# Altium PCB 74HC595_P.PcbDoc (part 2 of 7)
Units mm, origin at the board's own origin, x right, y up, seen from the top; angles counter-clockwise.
Board outline 89.11 x 89.03 mm, 2 copper layers (Top Layer, Bottom Layer); 552 components, 23 nets, 1488 pads, 408 vias.
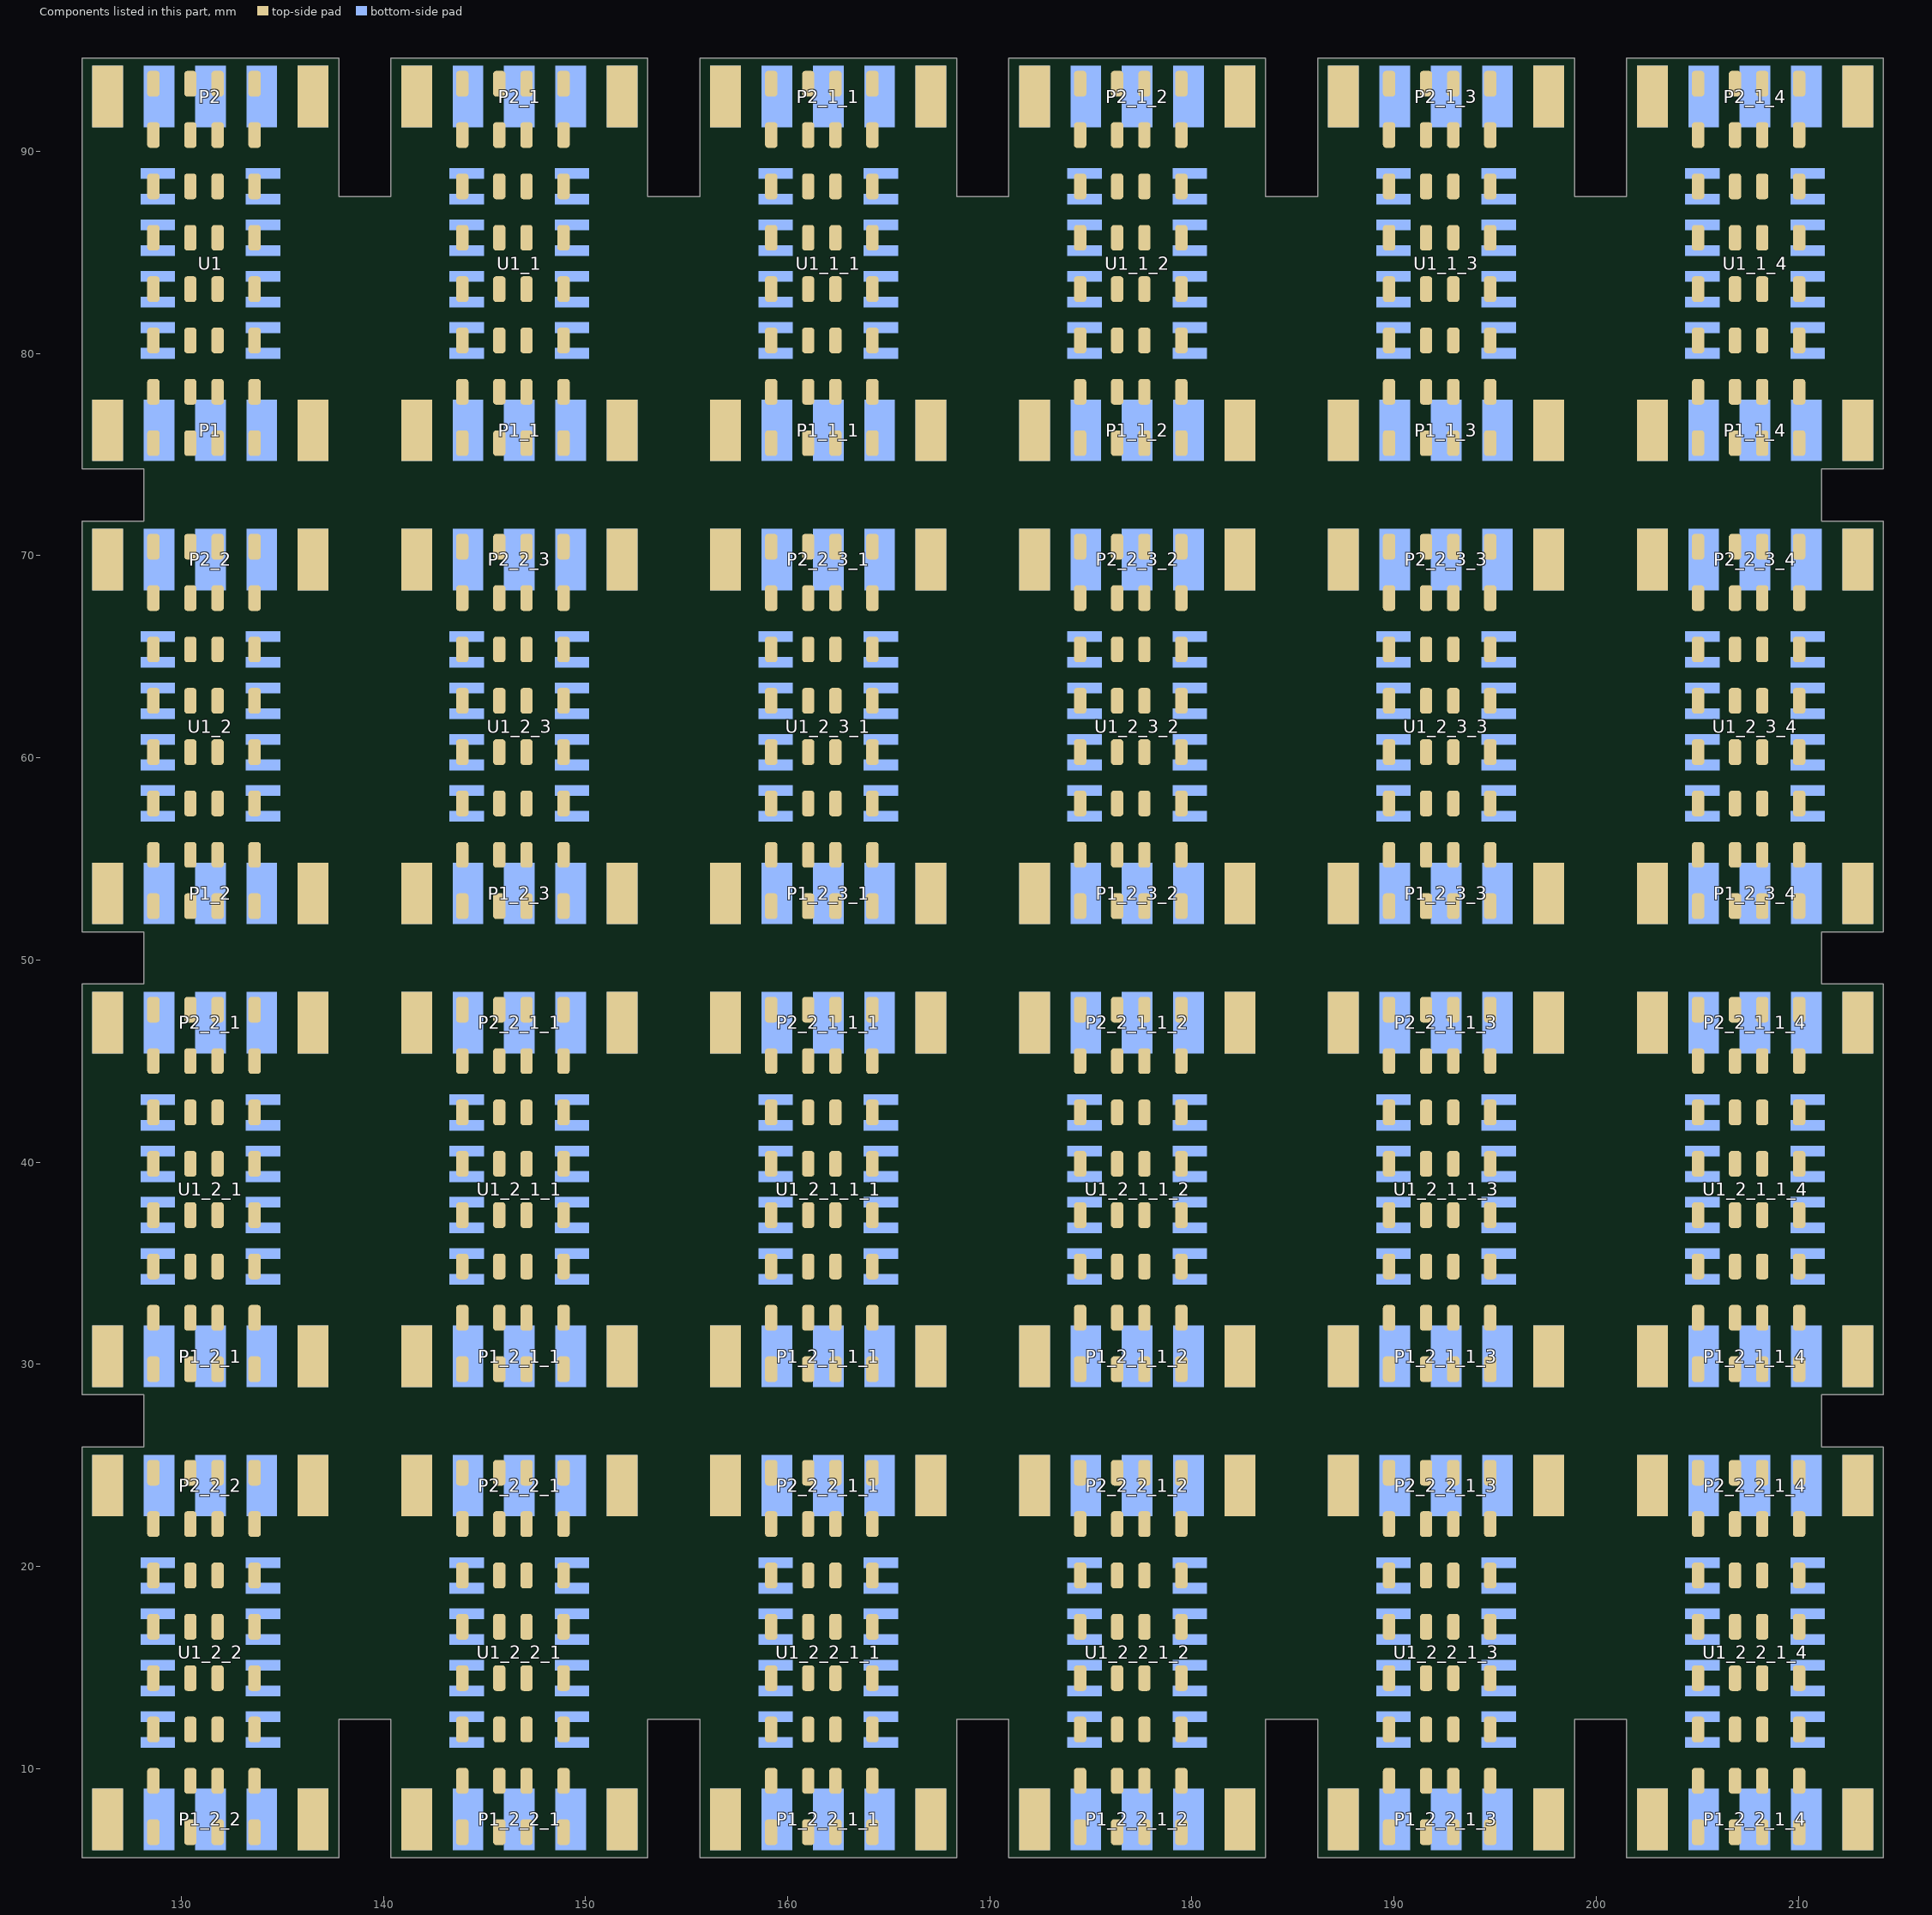
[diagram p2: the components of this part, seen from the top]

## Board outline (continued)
cut-out: 185.821,14.606 ccw(c186.096,14.606) 186.096,14.331 ccw(c186.096,14.606) 186.371,14.606 ccw(c186.096,14.606) 186.096,14.881 ccw(c186.096,14.606)
cut-out: 185.821,15.368 ccw(c186.096,15.368) 186.096,15.093 ccw(c186.096,15.368) 186.371,15.368 ccw(c186.096,15.368) 186.096,15.643 ccw(c186.096,15.368)
cut-out: 168.211,18.416 ccw(c168.486,18.416) 168.486,18.141 ccw(c168.486,18.416) 168.761,18.416 ccw(c168.486,18.416) 168.486,18.691 ccw(c168.486,18.416)
cut-out: 170.539,18.416 ccw(c170.814,18.416) 170.814,18.141 ccw(c170.814,18.416) 171.089,18.416 ccw(c170.814,18.416) 170.814,18.691 ccw(c170.814,18.416)
cut-out: 168.211,17.654 ccw(c168.486,17.654) 168.486,17.379 ccw(c168.486,17.654) 168.761,17.654 ccw(c168.486,17.654) 168.486,17.929 ccw(c168.486,17.654)
cut-out: 170.539,16.892 cw(c170.814,16.892) 170.814,17.167 cw(c170.814,16.892) 171.089,16.892 cw(c170.814,16.892) 170.814,16.617 cw(c170.814,16.892)
cut-out: 170.539,17.654 ccw(c170.814,17.654) 170.814,17.379 ccw(c170.814,17.654) 171.089,17.654 ccw(c170.814,17.654) 170.814,17.929 ccw(c170.814,17.654)
cut-out: 170.539,16.13 ccw(c170.814,16.13) 170.814,15.855 ccw(c170.814,16.13) 171.089,16.13 ccw(c170.814,16.13) 170.814,16.405 ccw(c170.814,16.13)
cut-out: 168.211,16.13 ccw(c168.486,16.13) 168.486,15.855 ccw(c168.486,16.13) 168.761,16.13 ccw(c168.486,16.13) 168.486,16.405 ccw(c168.486,16.13)
cut-out: 168.211,16.892 ccw(c168.486,16.892) 168.486,16.617 ccw(c168.486,16.892) 168.761,16.892 ccw(c168.486,16.892) 168.486,17.167 ccw(c168.486,16.892)
cut-out: 168.211,15.368 ccw(c168.486,15.368) 168.486,15.093 ccw(c168.486,15.368) 168.761,15.368 ccw(c168.486,15.368) 168.486,15.643 ccw(c168.486,15.368)
cut-out: 168.211,14.606 ccw(c168.486,14.606) 168.486,14.331 ccw(c168.486,14.606) 168.761,14.606 ccw(c168.486,14.606) 168.486,14.881 ccw(c168.486,14.606)
cut-out: 168.211,13.844 ccw(c168.486,13.844) 168.486,13.569 ccw(c168.486,13.844) 168.761,13.844 ccw(c168.486,13.844) 168.486,14.119 ccw(c168.486,13.844)
cut-out: 168.211,13.082 ccw(c168.486,13.082) 168.486,12.807 ccw(c168.486,13.082) 168.761,13.082 ccw(c168.486,13.082) 168.486,13.357 ccw(c168.486,13.082)
cut-out: 170.539,13.082 ccw(c170.814,13.082) 170.814,12.807 ccw(c170.814,13.082) 171.089,13.082 ccw(c170.814,13.082) 170.814,13.357 ccw(c170.814,13.082)
cut-out: 170.539,13.844 ccw(c170.814,13.844) 170.814,13.569 ccw(c170.814,13.844) 171.089,13.844 ccw(c170.814,13.844) 170.814,14.119 ccw(c170.814,13.844)
cut-out: 170.539,14.606 ccw(c170.814,14.606) 170.814,14.331 ccw(c170.814,14.606) 171.089,14.606 ccw(c170.814,14.606) 170.814,14.881 ccw(c170.814,14.606)
cut-out: 170.539,15.368 ccw(c170.814,15.368) 170.814,15.093 ccw(c170.814,15.368) 171.089,15.368 ccw(c170.814,15.368) 170.814,15.643 ccw(c170.814,15.368)
cut-out: 152.929,18.416 ccw(c153.204,18.416) 153.204,18.141 ccw(c153.204,18.416) 153.479,18.416 ccw(c153.204,18.416) 153.204,18.691 ccw(c153.204,18.416)
cut-out: 155.257,18.416 ccw(c155.532,18.416) 155.532,18.141 ccw(c155.532,18.416) 155.807,18.416 ccw(c155.532,18.416) 155.532,18.691 ccw(c155.532,18.416)
cut-out: 152.929,17.654 ccw(c153.204,17.654) 153.204,17.379 ccw(c153.204,17.654) 153.479,17.654 ccw(c153.204,17.654) 153.204,17.929 ccw(c153.204,17.654)
cut-out: 155.257,16.892 cw(c155.532,16.892) 155.532,17.167 cw(c155.532,16.892) 155.807,16.892 cw(c155.532,16.892) 155.532,16.617 cw(c155.532,16.892)
cut-out: 155.257,17.654 ccw(c155.532,17.654) 155.532,17.379 ccw(c155.532,17.654) 155.807,17.654 ccw(c155.532,17.654) 155.532,17.929 ccw(c155.532,17.654)
cut-out: 155.257,16.13 ccw(c155.532,16.13) 155.532,15.855 ccw(c155.532,16.13) 155.807,16.13 ccw(c155.532,16.13) 155.532,16.405 ccw(c155.532,16.13)
cut-out: 152.929,16.13 ccw(c153.204,16.13) 153.204,15.855 ccw(c153.204,16.13) 153.479,16.13 ccw(c153.204,16.13) 153.204,16.405 ccw(c153.204,16.13)
cut-out: 152.929,16.892 ccw(c153.204,16.892) 153.204,16.617 ccw(c153.204,16.892) 153.479,16.892 ccw(c153.204,16.892) 153.204,17.167 ccw(c153.204,16.892)
cut-out: 152.929,15.368 ccw(c153.204,15.368) 153.204,15.093 ccw(c153.204,15.368) 153.479,15.368 ccw(c153.204,15.368) 153.204,15.643 ccw(c153.204,15.368)
cut-out: 152.929,14.606 ccw(c153.204,14.606) 153.204,14.331 ccw(c153.204,14.606) 153.479,14.606 ccw(c153.204,14.606) 153.204,14.881 ccw(c153.204,14.606)
cut-out: 152.929,13.844 ccw(c153.204,13.844) 153.204,13.569 ccw(c153.204,13.844) 153.479,13.844 ccw(c153.204,13.844) 153.204,14.119 ccw(c153.204,13.844)
cut-out: 152.929,13.082 ccw(c153.204,13.082) 153.204,12.807 ccw(c153.204,13.082) 153.479,13.082 ccw(c153.204,13.082) 153.204,13.357 ccw(c153.204,13.082)
cut-out: 155.257,13.082 ccw(c155.532,13.082) 155.532,12.807 ccw(c155.532,13.082) 155.807,13.082 ccw(c155.532,13.082) 155.532,13.357 ccw(c155.532,13.082)
cut-out: 155.257,13.844 ccw(c155.532,13.844) 155.532,13.569 ccw(c155.532,13.844) 155.807,13.844 ccw(c155.532,13.844) 155.532,14.119 ccw(c155.532,13.844)
cut-out: 155.257,14.606 ccw(c155.532,14.606) 155.532,14.331 ccw(c155.532,14.606) 155.807,14.606 ccw(c155.532,14.606) 155.532,14.881 ccw(c155.532,14.606)
cut-out: 155.257,15.368 ccw(c155.532,15.368) 155.532,15.093 ccw(c155.532,15.368) 155.807,15.368 ccw(c155.532,15.368) 155.532,15.643 ccw(c155.532,15.368)
cut-out: 137.647,18.416 ccw(c137.922,18.416) 137.922,18.141 ccw(c137.922,18.416) 138.197,18.416 ccw(c137.922,18.416) 137.922,18.691 ccw(c137.922,18.416)
cut-out: 139.975,18.416 ccw(c140.25,18.416) 140.25,18.141 ccw(c140.25,18.416) 140.525,18.416 ccw(c140.25,18.416) 140.25,18.691 ccw(c140.25,18.416)
cut-out: 137.647,17.654 ccw(c137.922,17.654) 137.922,17.379 ccw(c137.922,17.654) 138.197,17.654 ccw(c137.922,17.654) 137.922,17.929 ccw(c137.922,17.654)
cut-out: 139.975,16.892 cw(c140.25,16.892) 140.25,17.167 cw(c140.25,16.892) 140.525,16.892 cw(c140.25,16.892) 140.25,16.617 cw(c140.25,16.892)
cut-out: 139.975,17.654 ccw(c140.25,17.654) 140.25,17.379 ccw(c140.25,17.654) 140.525,17.654 ccw(c140.25,17.654) 140.25,17.929 ccw(c140.25,17.654)
cut-out: 139.975,16.13 ccw(c140.25,16.13) 140.25,15.855 ccw(c140.25,16.13) 140.525,16.13 ccw(c140.25,16.13) 140.25,16.405 ccw(c140.25,16.13)
cut-out: 137.647,16.13 ccw(c137.922,16.13) 137.922,15.855 ccw(c137.922,16.13) 138.197,16.13 ccw(c137.922,16.13) 137.922,16.405 ccw(c137.922,16.13)
cut-out: 137.647,16.892 ccw(c137.922,16.892) 137.922,16.617 ccw(c137.922,16.892) 138.197,16.892 ccw(c137.922,16.892) 137.922,17.167 ccw(c137.922,16.892)
cut-out: 137.647,15.368 ccw(c137.922,15.368) 137.922,15.093 ccw(c137.922,15.368) 138.197,15.368 ccw(c137.922,15.368) 137.922,15.643 ccw(c137.922,15.368)
cut-out: 137.647,14.606 ccw(c137.922,14.606) 137.922,14.331 ccw(c137.922,14.606) 138.197,14.606 ccw(c137.922,14.606) 137.922,14.881 ccw(c137.922,14.606)
cut-out: 137.647,13.844 ccw(c137.922,13.844) 137.922,13.569 ccw(c137.922,13.844) 138.197,13.844 ccw(c137.922,13.844) 137.922,14.119 ccw(c137.922,13.844)
cut-out: 137.647,13.082 ccw(c137.922,13.082) 137.922,12.807 ccw(c137.922,13.082) 138.197,13.082 ccw(c137.922,13.082) 137.922,13.357 ccw(c137.922,13.082)
cut-out: 139.975,13.082 ccw(c140.25,13.082) 140.25,12.807 ccw(c140.25,13.082) 140.525,13.082 ccw(c140.25,13.082) 140.25,13.357 ccw(c140.25,13.082)
cut-out: 139.975,13.844 ccw(c140.25,13.844) 140.25,13.569 ccw(c140.25,13.844) 140.525,13.844 ccw(c140.25,13.844) 140.25,14.119 ccw(c140.25,13.844)
cut-out: 139.975,14.606 ccw(c140.25,14.606) 140.25,14.331 ccw(c140.25,14.606) 140.525,14.606 ccw(c140.25,14.606) 140.25,14.881 ccw(c140.25,14.606)
cut-out: 139.975,15.368 ccw(c140.25,15.368) 140.25,15.093 ccw(c140.25,15.368) 140.525,15.368 ccw(c140.25,15.368) 140.25,15.643 ccw(c140.25,15.368)
cut-out: 198.775,41.318 ccw(c199.05,41.318) 199.05,41.043 ccw(c199.05,41.318) 199.325,41.318 ccw(c199.05,41.318) 199.05,41.593 ccw(c199.05,41.318)
cut-out: 201.103,41.318 ccw(c201.378,41.318) 201.378,41.043 ccw(c201.378,41.318) 201.653,41.318 ccw(c201.378,41.318) 201.378,41.593 ccw(c201.378,41.318)
cut-out: 198.775,40.556 ccw(c199.05,40.556) 199.05,40.281 ccw(c199.05,40.556) 199.325,40.556 ccw(c199.05,40.556) 199.05,40.831 ccw(c199.05,40.556)
cut-out: 201.103,39.794 cw(c201.378,39.794) 201.378,40.069 cw(c201.378,39.794) 201.653,39.794 cw(c201.378,39.794) 201.378,39.519 cw(c201.378,39.794)
cut-out: 201.103,40.556 ccw(c201.378,40.556) 201.378,40.281 ccw(c201.378,40.556) 201.653,40.556 ccw(c201.378,40.556) 201.378,40.831 ccw(c201.378,40.556)
cut-out: 201.103,39.032 ccw(c201.378,39.032) 201.378,38.757 ccw(c201.378,39.032) 201.653,39.032 ccw(c201.378,39.032) 201.378,39.307 ccw(c201.378,39.032)
cut-out: 198.775,39.032 ccw(c199.05,39.032) 199.05,38.757 ccw(c199.05,39.032) 199.325,39.032 ccw(c199.05,39.032) 199.05,39.307 ccw(c199.05,39.032)
cut-out: 198.775,39.794 ccw(c199.05,39.794) 199.05,39.519 ccw(c199.05,39.794) 199.325,39.794 ccw(c199.05,39.794) 199.05,40.069 ccw(c199.05,39.794)
cut-out: 198.775,38.27 ccw(c199.05,38.27) 199.05,37.995 ccw(c199.05,38.27) 199.325,38.27 ccw(c199.05,38.27) 199.05,38.545 ccw(c199.05,38.27)
cut-out: 198.775,37.508 ccw(c199.05,37.508) 199.05,37.233 ccw(c199.05,37.508) 199.325,37.508 ccw(c199.05,37.508) 199.05,37.783 ccw(c199.05,37.508)
cut-out: 198.775,36.746 ccw(c199.05,36.746) 199.05,36.471 ccw(c199.05,36.746) 199.325,36.746 ccw(c199.05,36.746) 199.05,37.021 ccw(c199.05,36.746)
cut-out: 198.775,35.984 ccw(c199.05,35.984) 199.05,35.709 ccw(c199.05,35.984) 199.325,35.984 ccw(c199.05,35.984) 199.05,36.259 ccw(c199.05,35.984)
cut-out: 201.103,35.984 ccw(c201.378,35.984) 201.378,35.709 ccw(c201.378,35.984) 201.653,35.984 ccw(c201.378,35.984) 201.378,36.259 ccw(c201.378,35.984)
cut-out: 201.103,36.746 ccw(c201.378,36.746) 201.378,36.471 ccw(c201.378,36.746) 201.653,36.746 ccw(c201.378,36.746) 201.378,37.021 ccw(c201.378,36.746)
cut-out: 201.103,37.508 ccw(c201.378,37.508) 201.378,37.233 ccw(c201.378,37.508) 201.653,37.508 ccw(c201.378,37.508) 201.378,37.783 ccw(c201.378,37.508)
cut-out: 201.103,38.27 ccw(c201.378,38.27) 201.378,37.995 ccw(c201.378,38.27) 201.653,38.27 ccw(c201.378,38.27) 201.378,38.545 ccw(c201.378,38.27)
cut-out: 183.493,41.318 ccw(c183.768,41.318) 183.768,41.043 ccw(c183.768,41.318) 184.043,41.318 ccw(c183.768,41.318) 183.768,41.593 ccw(c183.768,41.318)
cut-out: 185.821,41.318 ccw(c186.096,41.318) 186.096,41.043 ccw(c186.096,41.318) 186.371,41.318 ccw(c186.096,41.318) 186.096,41.593 ccw(c186.096,41.318)
cut-out: 183.493,40.556 ccw(c183.768,40.556) 183.768,40.281 ccw(c183.768,40.556) 184.043,40.556 ccw(c183.768,40.556) 183.768,40.831 ccw(c183.768,40.556)
cut-out: 185.821,39.794 cw(c186.096,39.794) 186.096,40.069 cw(c186.096,39.794) 186.371,39.794 cw(c186.096,39.794) 186.096,39.519 cw(c186.096,39.794)
cut-out: 185.821,40.556 ccw(c186.096,40.556) 186.096,40.281 ccw(c186.096,40.556) 186.371,40.556 ccw(c186.096,40.556) 186.096,40.831 ccw(c186.096,40.556)
cut-out: 185.821,39.032 ccw(c186.096,39.032) 186.096,38.757 ccw(c186.096,39.032) 186.371,39.032 ccw(c186.096,39.032) 186.096,39.307 ccw(c186.096,39.032)
cut-out: 183.493,39.032 ccw(c183.768,39.032) 183.768,38.757 ccw(c183.768,39.032) 184.043,39.032 ccw(c183.768,39.032) 183.768,39.307 ccw(c183.768,39.032)
cut-out: 183.493,39.794 ccw(c183.768,39.794) 183.768,39.519 ccw(c183.768,39.794) 184.043,39.794 ccw(c183.768,39.794) 183.768,40.069 ccw(c183.768,39.794)
cut-out: 183.493,38.27 ccw(c183.768,38.27) 183.768,37.995 ccw(c183.768,38.27) 184.043,38.27 ccw(c183.768,38.27) 183.768,38.545 ccw(c183.768,38.27)
cut-out: 183.493,37.508 ccw(c183.768,37.508) 183.768,37.233 ccw(c183.768,37.508) 184.043,37.508 ccw(c183.768,37.508) 183.768,37.783 ccw(c183.768,37.508)
cut-out: 183.493,36.746 ccw(c183.768,36.746) 183.768,36.471 ccw(c183.768,36.746) 184.043,36.746 ccw(c183.768,36.746) 183.768,37.021 ccw(c183.768,36.746)
cut-out: 183.493,35.984 ccw(c183.768,35.984) 183.768,35.709 ccw(c183.768,35.984) 184.043,35.984 ccw(c183.768,35.984) 183.768,36.259 ccw(c183.768,35.984)
cut-out: 185.821,35.984 ccw(c186.096,35.984) 186.096,35.709 ccw(c186.096,35.984) 186.371,35.984 ccw(c186.096,35.984) 186.096,36.259 ccw(c186.096,35.984)
cut-out: 185.821,36.746 ccw(c186.096,36.746) 186.096,36.471 ccw(c186.096,36.746) 186.371,36.746 ccw(c186.096,36.746) 186.096,37.021 ccw(c186.096,36.746)
cut-out: 185.821,37.508 ccw(c186.096,37.508) 186.096,37.233 ccw(c186.096,37.508) 186.371,37.508 ccw(c186.096,37.508) 186.096,37.783 ccw(c186.096,37.508)
cut-out: 185.821,38.27 ccw(c186.096,38.27) 186.096,37.995 ccw(c186.096,38.27) 186.371,38.27 ccw(c186.096,38.27) 186.096,38.545 ccw(c186.096,38.27)
cut-out: 168.211,41.318 ccw(c168.486,41.318) 168.486,41.043 ccw(c168.486,41.318) 168.761,41.318 ccw(c168.486,41.318) 168.486,41.593 ccw(c168.486,41.318)
cut-out: 170.539,41.318 ccw(c170.814,41.318) 170.814,41.043 ccw(c170.814,41.318) 171.089,41.318 ccw(c170.814,41.318) 170.814,41.593 ccw(c170.814,41.318)
cut-out: 168.211,40.556 ccw(c168.486,40.556) 168.486,40.281 ccw(c168.486,40.556) 168.761,40.556 ccw(c168.486,40.556) 168.486,40.831 ccw(c168.486,40.556)
cut-out: 170.539,39.794 cw(c170.814,39.794) 170.814,40.069 cw(c170.814,39.794) 171.089,39.794 cw(c170.814,39.794) 170.814,39.519 cw(c170.814,39.794)
cut-out: 170.539,40.556 ccw(c170.814,40.556) 170.814,40.281 ccw(c170.814,40.556) 171.089,40.556 ccw(c170.814,40.556) 170.814,40.831 ccw(c170.814,40.556)
cut-out: 170.539,39.032 ccw(c170.814,39.032) 170.814,38.757 ccw(c170.814,39.032) 171.089,39.032 ccw(c170.814,39.032) 170.814,39.307 ccw(c170.814,39.032)
cut-out: 168.211,39.032 ccw(c168.486,39.032) 168.486,38.757 ccw(c168.486,39.032) 168.761,39.032 ccw(c168.486,39.032) 168.486,39.307 ccw(c168.486,39.032)
cut-out: 168.211,39.794 ccw(c168.486,39.794) 168.486,39.519 ccw(c168.486,39.794) 168.761,39.794 ccw(c168.486,39.794) 168.486,40.069 ccw(c168.486,39.794)
cut-out: 168.211,38.27 ccw(c168.486,38.27) 168.486,37.995 ccw(c168.486,38.27) 168.761,38.27 ccw(c168.486,38.27) 168.486,38.545 ccw(c168.486,38.27)
cut-out: 168.211,37.508 ccw(c168.486,37.508) 168.486,37.233 ccw(c168.486,37.508) 168.761,37.508 ccw(c168.486,37.508) 168.486,37.783 ccw(c168.486,37.508)
cut-out: 168.211,36.746 ccw(c168.486,36.746) 168.486,36.471 ccw(c168.486,36.746) 168.761,36.746 ccw(c168.486,36.746) 168.486,37.021 ccw(c168.486,36.746)
cut-out: 168.211,35.984 ccw(c168.486,35.984) 168.486,35.709 ccw(c168.486,35.984) 168.761,35.984 ccw(c168.486,35.984) 168.486,36.259 ccw(c168.486,35.984)
cut-out: 170.539,35.984 ccw(c170.814,35.984) 170.814,35.709 ccw(c170.814,35.984) 171.089,35.984 ccw(c170.814,35.984) 170.814,36.259 ccw(c170.814,35.984)
cut-out: 170.539,36.746 ccw(c170.814,36.746) 170.814,36.471 ccw(c170.814,36.746) 171.089,36.746 ccw(c170.814,36.746) 170.814,37.021 ccw(c170.814,36.746)
cut-out: 170.539,37.508 ccw(c170.814,37.508) 170.814,37.233 ccw(c170.814,37.508) 171.089,37.508 ccw(c170.814,37.508) 170.814,37.783 ccw(c170.814,37.508)
cut-out: 170.539,38.27 ccw(c170.814,38.27) 170.814,37.995 ccw(c170.814,38.27) 171.089,38.27 ccw(c170.814,38.27) 170.814,38.545 ccw(c170.814,38.27)
cut-out: 152.929,41.318 ccw(c153.204,41.318) 153.204,41.043 ccw(c153.204,41.318) 153.479,41.318 ccw(c153.204,41.318) 153.204,41.593 ccw(c153.204,41.318)
cut-out: 155.257,41.318 ccw(c155.532,41.318) 155.532,41.043 ccw(c155.532,41.318) 155.807,41.318 ccw(c155.532,41.318) 155.532,41.593 ccw(c155.532,41.318)
cut-out: 152.929,40.556 ccw(c153.204,40.556) 153.204,40.281 ccw(c153.204,40.556) 153.479,40.556 ccw(c153.204,40.556) 153.204,40.831 ccw(c153.204,40.556)
cut-out: 155.257,39.794 cw(c155.532,39.794) 155.532,40.069 cw(c155.532,39.794) 155.807,39.794 cw(c155.532,39.794) 155.532,39.519 cw(c155.532,39.794)
cut-out: 155.257,40.556 ccw(c155.532,40.556) 155.532,40.281 ccw(c155.532,40.556) 155.807,40.556 ccw(c155.532,40.556) 155.532,40.831 ccw(c155.532,40.556)
cut-out: 155.257,39.032 ccw(c155.532,39.032) 155.532,38.757 ccw(c155.532,39.032) 155.807,39.032 ccw(c155.532,39.032) 155.532,39.307 ccw(c155.532,39.032)
cut-out: 152.929,39.032 ccw(c153.204,39.032) 153.204,38.757 ccw(c153.204,39.032) 153.479,39.032 ccw(c153.204,39.032) 153.204,39.307 ccw(c153.204,39.032)
cut-out: 152.929,39.794 ccw(c153.204,39.794) 153.204,39.519 ccw(c153.204,39.794) 153.479,39.794 ccw(c153.204,39.794) 153.204,40.069 ccw(c153.204,39.794)
cut-out: 152.929,38.27 ccw(c153.204,38.27) 153.204,37.995 ccw(c153.204,38.27) 153.479,38.27 ccw(c153.204,38.27) 153.204,38.545 ccw(c153.204,38.27)
cut-out: 152.929,37.508 ccw(c153.204,37.508) 153.204,37.233 ccw(c153.204,37.508) 153.479,37.508 ccw(c153.204,37.508) 153.204,37.783 ccw(c153.204,37.508)
cut-out: 152.929,36.746 ccw(c153.204,36.746) 153.204,36.471 ccw(c153.204,36.746) 153.479,36.746 ccw(c153.204,36.746) 153.204,37.021 ccw(c153.204,36.746)
cut-out: 152.929,35.984 ccw(c153.204,35.984) 153.204,35.709 ccw(c153.204,35.984) 153.479,35.984 ccw(c153.204,35.984) 153.204,36.259 ccw(c153.204,35.984)
cut-out: 155.257,35.984 ccw(c155.532,35.984) 155.532,35.709 ccw(c155.532,35.984) 155.807,35.984 ccw(c155.532,35.984) 155.532,36.259 ccw(c155.532,35.984)
cut-out: 155.257,36.746 ccw(c155.532,36.746) 155.532,36.471 ccw(c155.532,36.746) 155.807,36.746 ccw(c155.532,36.746) 155.532,37.021 ccw(c155.532,36.746)
cut-out: 155.257,37.508 ccw(c155.532,37.508) 155.532,37.233 ccw(c155.532,37.508) 155.807,37.508 ccw(c155.532,37.508) 155.532,37.783 ccw(c155.532,37.508)
cut-out: 155.257,38.27 ccw(c155.532,38.27) 155.532,37.995 ccw(c155.532,38.27) 155.807,38.27 ccw(c155.532,38.27) 155.532,38.545 ccw(c155.532,38.27)
cut-out: 137.647,41.318 ccw(c137.922,41.318) 137.922,41.043 ccw(c137.922,41.318) 138.197,41.318 ccw(c137.922,41.318) 137.922,41.593 ccw(c137.922,41.318)
cut-out: 139.975,41.318 ccw(c140.25,41.318) 140.25,41.043 ccw(c140.25,41.318) 140.525,41.318 ccw(c140.25,41.318) 140.25,41.593 ccw(c140.25,41.318)
cut-out: 137.647,40.556 ccw(c137.922,40.556) 137.922,40.281 ccw(c137.922,40.556) 138.197,40.556 ccw(c137.922,40.556) 137.922,40.831 ccw(c137.922,40.556)
cut-out: 139.975,39.794 cw(c140.25,39.794) 140.25,40.069 cw(c140.25,39.794) 140.525,39.794 cw(c140.25,39.794) 140.25,39.519 cw(c140.25,39.794)
cut-out: 139.975,40.556 ccw(c140.25,40.556) 140.25,40.281 ccw(c140.25,40.556) 140.525,40.556 ccw(c140.25,40.556) 140.25,40.831 ccw(c140.25,40.556)
cut-out: 139.975,39.032 ccw(c140.25,39.032) 140.25,38.757 ccw(c140.25,39.032) 140.525,39.032 ccw(c140.25,39.032) 140.25,39.307 ccw(c140.25,39.032)
cut-out: 137.647,39.032 ccw(c137.922,39.032) 137.922,38.757 ccw(c137.922,39.032) 138.197,39.032 ccw(c137.922,39.032) 137.922,39.307 ccw(c137.922,39.032)
cut-out: 137.647,39.794 ccw(c137.922,39.794) 137.922,39.519 ccw(c137.922,39.794) 138.197,39.794 ccw(c137.922,39.794) 137.922,40.069 ccw(c137.922,39.794)
cut-out: 137.647,38.27 ccw(c137.922,38.27) 137.922,37.995 ccw(c137.922,38.27) 138.197,38.27 ccw(c137.922,38.27) 137.922,38.545 ccw(c137.922,38.27)
cut-out: 137.647,37.508 ccw(c137.922,37.508) 137.922,37.233 ccw(c137.922,37.508) 138.197,37.508 ccw(c137.922,37.508) 137.922,37.783 ccw(c137.922,37.508)
cut-out: 137.647,36.746 ccw(c137.922,36.746) 137.922,36.471 ccw(c137.922,36.746) 138.197,36.746 ccw(c137.922,36.746) 137.922,37.021 ccw(c137.922,36.746)
cut-out: 137.647,35.984 ccw(c137.922,35.984) 137.922,35.709 ccw(c137.922,35.984) 138.197,35.984 ccw(c137.922,35.984) 137.922,36.259 ccw(c137.922,35.984)
cut-out: 139.975,35.984 ccw(c140.25,35.984) 140.25,35.709 ccw(c140.25,35.984) 140.525,35.984 ccw(c140.25,35.984) 140.25,36.259 ccw(c140.25,35.984)
cut-out: 139.975,36.746 ccw(c140.25,36.746) 140.25,36.471 ccw(c140.25,36.746) 140.525,36.746 ccw(c140.25,36.746) 140.25,37.021 ccw(c140.25,36.746)
cut-out: 139.975,37.508 ccw(c140.25,37.508) 140.25,37.233 ccw(c140.25,37.508) 140.525,37.508 ccw(c140.25,37.508) 140.25,37.783 ccw(c140.25,37.508)
cut-out: 139.975,38.27 ccw(c140.25,38.27) 140.25,37.995 ccw(c140.25,38.27) 140.525,38.27 ccw(c140.25,38.27) 140.25,38.545 ccw(c140.25,38.27)
cut-out: 198.775,64.22 ccw(c199.05,64.22) 199.05,63.945 ccw(c199.05,64.22) 199.325,64.22 ccw(c199.05,64.22) 199.05,64.495 ccw(c199.05,64.22)
cut-out: 201.103,64.22 ccw(c201.378,64.22) 201.378,63.945 ccw(c201.378,64.22) 201.653,64.22 ccw(c201.378,64.22) 201.378,64.495 ccw(c201.378,64.22)
cut-out: 198.775,63.458 ccw(c199.05,63.458) 199.05,63.183 ccw(c199.05,63.458) 199.325,63.458 ccw(c199.05,63.458) 199.05,63.733 ccw(c199.05,63.458)
cut-out: 201.103,62.696 cw(c201.378,62.696) 201.378,62.971 cw(c201.378,62.696) 201.653,62.696 cw(c201.378,62.696) 201.378,62.421 cw(c201.378,62.696)
cut-out: 201.103,63.458 ccw(c201.378,63.458) 201.378,63.183 ccw(c201.378,63.458) 201.653,63.458 ccw(c201.378,63.458) 201.378,63.733 ccw(c201.378,63.458)
cut-out: 201.103,61.934 ccw(c201.378,61.934) 201.378,61.659 ccw(c201.378,61.934) 201.653,61.934 ccw(c201.378,61.934) 201.378,62.209 ccw(c201.378,61.934)
cut-out: 198.775,61.934 ccw(c199.05,61.934) 199.05,61.659 ccw(c199.05,61.934) 199.325,61.934 ccw(c199.05,61.934) 199.05,62.209 ccw(c199.05,61.934)
cut-out: 198.775,62.696 ccw(c199.05,62.696) 199.05,62.421 ccw(c199.05,62.696) 199.325,62.696 ccw(c199.05,62.696) 199.05,62.971 ccw(c199.05,62.696)
cut-out: 198.775,61.172 ccw(c199.05,61.172) 199.05,60.897 ccw(c199.05,61.172) 199.325,61.172 ccw(c199.05,61.172) 199.05,61.447 ccw(c199.05,61.172)
cut-out: 198.775,60.41 ccw(c199.05,60.41) 199.05,60.135 ccw(c199.05,60.41) 199.325,60.41 ccw(c199.05,60.41) 199.05,60.685 ccw(c199.05,60.41)
cut-out: 198.775,59.648 ccw(c199.05,59.648) 199.05,59.373 ccw(c199.05,59.648) 199.325,59.648 ccw(c199.05,59.648) 199.05,59.923 ccw(c199.05,59.648)
cut-out: 198.775,58.886 ccw(c199.05,58.886) 199.05,58.611 ccw(c199.05,58.886) 199.325,58.886 ccw(c199.05,58.886) 199.05,59.161 ccw(c199.05,58.886)
cut-out: 201.103,58.886 ccw(c201.378,58.886) 201.378,58.611 ccw(c201.378,58.886) 201.653,58.886 ccw(c201.378,58.886) 201.378,59.161 ccw(c201.378,58.886)
cut-out: 201.103,59.648 ccw(c201.378,59.648) 201.378,59.373 ccw(c201.378,59.648) 201.653,59.648 ccw(c201.378,59.648) 201.378,59.923 ccw(c201.378,59.648)
cut-out: 201.103,60.41 ccw(c201.378,60.41) 201.378,60.135 ccw(c201.378,60.41) 201.653,60.41 ccw(c201.378,60.41) 201.378,60.685 ccw(c201.378,60.41)
cut-out: 201.103,61.172 ccw(c201.378,61.172) 201.378,60.897 ccw(c201.378,61.172) 201.653,61.172 ccw(c201.378,61.172) 201.378,61.447 ccw(c201.378,61.172)
cut-out: 183.493,64.22 ccw(c183.768,64.22) 183.768,63.945 ccw(c183.768,64.22) 184.043,64.22 ccw(c183.768,64.22) 183.768,64.495 ccw(c183.768,64.22)
cut-out: 185.821,64.22 ccw(c186.096,64.22) 186.096,63.945 ccw(c186.096,64.22) 186.371,64.22 ccw(c186.096,64.22) 186.096,64.495 ccw(c186.096,64.22)
cut-out: 183.493,63.458 ccw(c183.768,63.458) 183.768,63.183 ccw(c183.768,63.458) 184.043,63.458 ccw(c183.768,63.458) 183.768,63.733 ccw(c183.768,63.458)
cut-out: 185.821,62.696 cw(c186.096,62.696) 186.096,62.971 cw(c186.096,62.696) 186.371,62.696 cw(c186.096,62.696) 186.096,62.421 cw(c186.096,62.696)
cut-out: 185.821,63.458 ccw(c186.096,63.458) 186.096,63.183 ccw(c186.096,63.458) 186.371,63.458 ccw(c186.096,63.458) 186.096,63.733 ccw(c186.096,63.458)
cut-out: 185.821,61.934 ccw(c186.096,61.934) 186.096,61.659 ccw(c186.096,61.934) 186.371,61.934 ccw(c186.096,61.934) 186.096,62.209 ccw(c186.096,61.934)
cut-out: 183.493,61.934 ccw(c183.768,61.934) 183.768,61.659 ccw(c183.768,61.934) 184.043,61.934 ccw(c183.768,61.934) 183.768,62.209 ccw(c183.768,61.934)
cut-out: 183.493,62.696 ccw(c183.768,62.696) 183.768,62.421 ccw(c183.768,62.696) 184.043,62.696 ccw(c183.768,62.696) 183.768,62.971 ccw(c183.768,62.696)
cut-out: 183.493,61.172 ccw(c183.768,61.172) 183.768,60.897 ccw(c183.768,61.172) 184.043,61.172 ccw(c183.768,61.172) 183.768,61.447 ccw(c183.768,61.172)
cut-out: 183.493,60.41 ccw(c183.768,60.41) 183.768,60.135 ccw(c183.768,60.41) 184.043,60.41 ccw(c183.768,60.41) 183.768,60.685 ccw(c183.768,60.41)
cut-out: 183.493,59.648 ccw(c183.768,59.648) 183.768,59.373 ccw(c183.768,59.648) 184.043,59.648 ccw(c183.768,59.648) 183.768,59.923 ccw(c183.768,59.648)
cut-out: 183.493,58.886 ccw(c183.768,58.886) 183.768,58.611 ccw(c183.768,58.886) 184.043,58.886 ccw(c183.768,58.886) 183.768,59.161 ccw(c183.768,58.886)
cut-out: 185.821,58.886 ccw(c186.096,58.886) 186.096,58.611 ccw(c186.096,58.886) 186.371,58.886 ccw(c186.096,58.886) 186.096,59.161 ccw(c186.096,58.886)
cut-out: 185.821,59.648 ccw(c186.096,59.648) 186.096,59.373 ccw(c186.096,59.648) 186.371,59.648 ccw(c186.096,59.648) 186.096,59.923 ccw(c186.096,59.648)
cut-out: 185.821,60.41 ccw(c186.096,60.41) 186.096,60.135 ccw(c186.096,60.41) 186.371,60.41 ccw(c186.096,60.41) 186.096,60.685 ccw(c186.096,60.41)
cut-out: 185.821,61.172 ccw(c186.096,61.172) 186.096,60.897 ccw(c186.096,61.172) 186.371,61.172 ccw(c186.096,61.172) 186.096,61.447 ccw(c186.096,61.172)
cut-out: 168.211,64.22 ccw(c168.486,64.22) 168.486,63.945 ccw(c168.486,64.22) 168.761,64.22 ccw(c168.486,64.22) 168.486,64.495 ccw(c168.486,64.22)
cut-out: 170.539,64.22 ccw(c170.814,64.22) 170.814,63.945 ccw(c170.814,64.22) 171.089,64.22 ccw(c170.814,64.22) 170.814,64.495 ccw(c170.814,64.22)
cut-out: 168.211,63.458 ccw(c168.486,63.458) 168.486,63.183 ccw(c168.486,63.458) 168.761,63.458 ccw(c168.486,63.458) 168.486,63.733 ccw(c168.486,63.458)
cut-out: 170.539,62.696 cw(c170.814,62.696) 170.814,62.971 cw(c170.814,62.696) 171.089,62.696 cw(c170.814,62.696) 170.814,62.421 cw(c170.814,62.696)
cut-out: 170.539,63.458 ccw(c170.814,63.458) 170.814,63.183 ccw(c170.814,63.458) 171.089,63.458 ccw(c170.814,63.458) 170.814,63.733 ccw(c170.814,63.458)
cut-out: 170.539,61.934 ccw(c170.814,61.934) 170.814,61.659 ccw(c170.814,61.934) 171.089,61.934 ccw(c170.814,61.934) 170.814,62.209 ccw(c170.814,61.934)
cut-out: 168.211,61.934 ccw(c168.486,61.934) 168.486,61.659 ccw(c168.486,61.934) 168.761,61.934 ccw(c168.486,61.934) 168.486,62.209 ccw(c168.486,61.934)
cut-out: 168.211,62.696 ccw(c168.486,62.696) 168.486,62.421 ccw(c168.486,62.696) 168.761,62.696 ccw(c168.486,62.696) 168.486,62.971 ccw(c168.486,62.696)
cut-out: 168.211,61.172 ccw(c168.486,61.172) 168.486,60.897 ccw(c168.486,61.172) 168.761,61.172 ccw(c168.486,61.172) 168.486,61.447 ccw(c168.486,61.172)
cut-out: 168.211,60.41 ccw(c168.486,60.41) 168.486,60.135 ccw(c168.486,60.41) 168.761,60.41 ccw(c168.486,60.41) 168.486,60.685 ccw(c168.486,60.41)
cut-out: 168.211,59.648 ccw(c168.486,59.648) 168.486,59.373 ccw(c168.486,59.648) 168.761,59.648 ccw(c168.486,59.648) 168.486,59.923 ccw(c168.486,59.648)
cut-out: 168.211,58.886 ccw(c168.486,58.886) 168.486,58.611 ccw(c168.486,58.886) 168.761,58.886 ccw(c168.486,58.886) 168.486,59.161 ccw(c168.486,58.886)
cut-out: 170.539,58.886 ccw(c170.814,58.886) 170.814,58.611 ccw(c170.814,58.886) 171.089,58.886 ccw(c170.814,58.886) 170.814,59.161 ccw(c170.814,58.886)
cut-out: 170.539,59.648 ccw(c170.814,59.648) 170.814,59.373 ccw(c170.814,59.648) 171.089,59.648 ccw(c170.814,59.648) 170.814,59.923 ccw(c170.814,59.648)
cut-out: 170.539,60.41 ccw(c170.814,60.41) 170.814,60.135 ccw(c170.814,60.41) 171.089,60.41 ccw(c170.814,60.41) 170.814,60.685 ccw(c170.814,60.41)
cut-out: 170.539,61.172 ccw(c170.814,61.172) 170.814,60.897 ccw(c170.814,61.172) 171.089,61.172 ccw(c170.814,61.172) 170.814,61.447 ccw(c170.814,61.172)
cut-out: 152.929,64.22 ccw(c153.204,64.22) 153.204,63.945 ccw(c153.204,64.22) 153.479,64.22 ccw(c153.204,64.22) 153.204,64.495 ccw(c153.204,64.22)
cut-out: 155.257,64.22 ccw(c155.532,64.22) 155.532,63.945 ccw(c155.532,64.22) 155.807,64.22 ccw(c155.532,64.22) 155.532,64.495 ccw(c155.532,64.22)
cut-out: 152.929,63.458 ccw(c153.204,63.458) 153.204,63.183 ccw(c153.204,63.458) 153.479,63.458 ccw(c153.204,63.458) 153.204,63.733 ccw(c153.204,63.458)
cut-out: 155.257,62.696 cw(c155.532,62.696) 155.532,62.971 cw(c155.532,62.696) 155.807,62.696 cw(c155.532,62.696) 155.532,62.421 cw(c155.532,62.696)
cut-out: 155.257,63.458 ccw(c155.532,63.458) 155.532,63.183 ccw(c155.532,63.458) 155.807,63.458 ccw(c155.532,63.458) 155.532,63.733 ccw(c155.532,63.458)
cut-out: 155.257,61.934 ccw(c155.532,61.934) 155.532,61.659 ccw(c155.532,61.934) 155.807,61.934 ccw(c155.532,61.934) 155.532,62.209 ccw(c155.532,61.934)
cut-out: 152.929,61.934 ccw(c153.204,61.934) 153.204,61.659 ccw(c153.204,61.934) 153.479,61.934 ccw(c153.204,61.934) 153.204,62.209 ccw(c153.204,61.934)
cut-out: 152.929,62.696 ccw(c153.204,62.696) 153.204,62.421 ccw(c153.204,62.696) 153.479,62.696 ccw(c153.204,62.696) 153.204,62.971 ccw(c153.204,62.696)
cut-out: 152.929,61.172 ccw(c153.204,61.172) 153.204,60.897 ccw(c153.204,61.172) 153.479,61.172 ccw(c153.204,61.172) 153.204,61.447 ccw(c153.204,61.172)
cut-out: 152.929,60.41 ccw(c153.204,60.41) 153.204,60.135 ccw(c153.204,60.41) 153.479,60.41 ccw(c153.204,60.41) 153.204,60.685 ccw(c153.204,60.41)
cut-out: 152.929,59.648 ccw(c153.204,59.648) 153.204,59.373 ccw(c153.204,59.648) 153.479,59.648 ccw(c153.204,59.648) 153.204,59.923 ccw(c153.204,59.648)
cut-out: 152.929,58.886 ccw(c153.204,58.886) 153.204,58.611 ccw(c153.204,58.886) 153.479,58.886 ccw(c153.204,58.886) 153.204,59.161 ccw(c153.204,58.886)
cut-out: 155.257,58.886 ccw(c155.532,58.886) 155.532,58.611 ccw(c155.532,58.886) 155.807,58.886 ccw(c155.532,58.886) 155.532,59.161 ccw(c155.532,58.886)
cut-out: 155.257,59.648 ccw(c155.532,59.648) 155.532,59.373 ccw(c155.532,59.648) 155.807,59.648 ccw(c155.532,59.648) 155.532,59.923 ccw(c155.532,59.648)
cut-out: 155.257,60.41 ccw(c155.532,60.41) 155.532,60.135 ccw(c155.532,60.41) 155.807,60.41 ccw(c155.532,60.41) 155.532,60.685 ccw(c155.532,60.41)
cut-out: 155.257,61.172 ccw(c155.532,61.172) 155.532,60.897 ccw(c155.532,61.172) 155.807,61.172 ccw(c155.532,61.172) 155.532,61.447 ccw(c155.532,61.172)
cut-out: 137.647,64.22 ccw(c137.922,64.22) 137.922,63.945 ccw(c137.922,64.22) 138.197,64.22 ccw(c137.922,64.22) 137.922,64.495 ccw(c137.922,64.22)
cut-out: 139.975,64.22 ccw(c140.25,64.22) 140.25,63.945 ccw(c140.25,64.22) 140.525,64.22 ccw(c140.25,64.22) 140.25,64.495 ccw(c140.25,64.22)
cut-out: 137.647,63.458 ccw(c137.922,63.458) 137.922,63.183 ccw(c137.922,63.458) 138.197,63.458 ccw(c137.922,63.458) 137.922,63.733 ccw(c137.922,63.458)
cut-out: 139.975,62.696 cw(c140.25,62.696) 140.25,62.971 cw(c140.25,62.696) 140.525,62.696 cw(c140.25,62.696) 140.25,62.421 cw(c140.25,62.696)
cut-out: 139.975,63.458 ccw(c140.25,63.458) 140.25,63.183 ccw(c140.25,63.458) 140.525,63.458 ccw(c140.25,63.458) 140.25,63.733 ccw(c140.25,63.458)
cut-out: 139.975,61.934 ccw(c140.25,61.934) 140.25,61.659 ccw(c140.25,61.934) 140.525,61.934 ccw(c140.25,61.934) 140.25,62.209 ccw(c140.25,61.934)
cut-out: 137.647,61.934 ccw(c137.922,61.934) 137.922,61.659 ccw(c137.922,61.934) 138.197,61.934 ccw(c137.922,61.934) 137.922,62.209 ccw(c137.922,61.934)
cut-out: 137.647,62.696 ccw(c137.922,62.696) 137.922,62.421 ccw(c137.922,62.696) 138.197,62.696 ccw(c137.922,62.696) 137.922,62.971 ccw(c137.922,62.696)
cut-out: 137.647,61.172 ccw(c137.922,61.172) 137.922,60.897 ccw(c137.922,61.172) 138.197,61.172 ccw(c137.922,61.172) 137.922,61.447 ccw(c137.922,61.172)
cut-out: 137.647,60.41 ccw(c137.922,60.41) 137.922,60.135 ccw(c137.922,60.41) 138.197,60.41 ccw(c137.922,60.41) 137.922,60.685 ccw(c137.922,60.41)
cut-out: 137.647,59.648 ccw(c137.922,59.648) 137.922,59.373 ccw(c137.922,59.648) 138.197,59.648 ccw(c137.922,59.648) 137.922,59.923 ccw(c137.922,59.648)
cut-out: 137.647,58.886 ccw(c137.922,58.886) 137.922,58.611 ccw(c137.922,58.886) 138.197,58.886 ccw(c137.922,58.886) 137.922,59.161 ccw(c137.922,58.886)
cut-out: 139.975,58.886 ccw(c140.25,58.886) 140.25,58.611 ccw(c140.25,58.886) 140.525,58.886 ccw(c140.25,58.886) 140.25,59.161 ccw(c140.25,58.886)
cut-out: 139.975,59.648 ccw(c140.25,59.648) 140.25,59.373 ccw(c140.25,59.648) 140.525,59.648 ccw(c140.25,59.648) 140.25,59.923 ccw(c140.25,59.648)
cut-out: 139.975,60.41 ccw(c140.25,60.41) 140.25,60.135 ccw(c140.25,60.41) 140.525,60.41 ccw(c140.25,60.41) 140.25,60.685 ccw(c140.25,60.41)
cut-out: 139.975,61.172 ccw(c140.25,61.172) 140.25,60.897 ccw(c140.25,61.172) 140.525,61.172 ccw(c140.25,61.172) 140.25,61.447 ccw(c140.25,61.172)
cut-out: 198.775,87.122 ccw(c199.05,87.122) 199.05,86.847 ccw(c199.05,87.122) 199.325,87.122 ccw(c199.05,87.122) 199.05,87.397 ccw(c199.05,87.122)
cut-out: 201.103,87.122 ccw(c201.378,87.122) 201.378,86.847 ccw(c201.378,87.122) 201.653,87.122 ccw(c201.378,87.122) 201.378,87.397 ccw(c201.378,87.122)
cut-out: 198.775,86.36 ccw(c199.05,86.36) 199.05,86.085 ccw(c199.05,86.36) 199.325,86.36 ccw(c199.05,86.36) 199.05,86.635 ccw(c199.05,86.36)
cut-out: 201.103,85.598 cw(c201.378,85.598) 201.378,85.873 cw(c201.378,85.598) 201.653,85.598 cw(c201.378,85.598) 201.378,85.323 cw(c201.378,85.598)
cut-out: 201.103,86.36 ccw(c201.378,86.36) 201.378,86.085 ccw(c201.378,86.36) 201.653,86.36 ccw(c201.378,86.36) 201.378,86.635 ccw(c201.378,86.36)
cut-out: 201.103,84.836 ccw(c201.378,84.836) 201.378,84.561 ccw(c201.378,84.836) 201.653,84.836 ccw(c201.378,84.836) 201.378,85.111 ccw(c201.378,84.836)
cut-out: 198.775,84.836 ccw(c199.05,84.836) 199.05,84.561 ccw(c199.05,84.836) 199.325,84.836 ccw(c199.05,84.836) 199.05,85.111 ccw(c199.05,84.836)
cut-out: 198.775,85.598 ccw(c199.05,85.598) 199.05,85.323 ccw(c199.05,85.598) 199.325,85.598 ccw(c199.05,85.598) 199.05,85.873 ccw(c199.05,85.598)
cut-out: 198.775,84.074 ccw(c199.05,84.074) 199.05,83.799 ccw(c199.05,84.074) 199.325,84.074 ccw(c199.05,84.074) 199.05,84.349 ccw(c199.05,84.074)
cut-out: 198.775,83.312 ccw(c199.05,83.312) 199.05,83.037 ccw(c199.05,83.312) 199.325,83.312 ccw(c199.05,83.312) 199.05,83.587 ccw(c199.05,83.312)
cut-out: 198.775,82.55 ccw(c199.05,82.55) 199.05,82.275 ccw(c199.05,82.55) 199.325,82.55 ccw(c199.05,82.55) 199.05,82.825 ccw(c199.05,82.55)
cut-out: 198.775,81.788 ccw(c199.05,81.788) 199.05,81.513 ccw(c199.05,81.788) 199.325,81.788 ccw(c199.05,81.788) 199.05,82.063 ccw(c199.05,81.788)
cut-out: 201.103,81.788 ccw(c201.378,81.788) 201.378,81.513 ccw(c201.378,81.788) 201.653,81.788 ccw(c201.378,81.788) 201.378,82.063 ccw(c201.378,81.788)
cut-out: 201.103,82.55 ccw(c201.378,82.55) 201.378,82.275 ccw(c201.378,82.55) 201.653,82.55 ccw(c201.378,82.55) 201.378,82.825 ccw(c201.378,82.55)
cut-out: 201.103,83.312 ccw(c201.378,83.312) 201.378,83.037 ccw(c201.378,83.312) 201.653,83.312 ccw(c201.378,83.312) 201.378,83.587 ccw(c201.378,83.312)
cut-out: 201.103,84.074 ccw(c201.378,84.074) 201.378,83.799 ccw(c201.378,84.074) 201.653,84.074 ccw(c201.378,84.074) 201.378,84.349 ccw(c201.378,84.074)
cut-out: 183.493,87.122 ccw(c183.768,87.122) 183.768,86.847 ccw(c183.768,87.122) 184.043,87.122 ccw(c183.768,87.122) 183.768,87.397 ccw(c183.768,87.122)
cut-out: 185.821,87.122 ccw(c186.096,87.122) 186.096,86.847 ccw(c186.096,87.122) 186.371,87.122 ccw(c186.096,87.122) 186.096,87.397 ccw(c186.096,87.122)
cut-out: 183.493,86.36 ccw(c183.768,86.36) 183.768,86.085 ccw(c183.768,86.36) 184.043,86.36 ccw(c183.768,86.36) 183.768,86.635 ccw(c183.768,86.36)
cut-out: 185.821,85.598 cw(c186.096,85.598) 186.096,85.873 cw(c186.096,85.598) 186.371,85.598 cw(c186.096,85.598) 186.096,85.323 cw(c186.096,85.598)
cut-out: 185.821,86.36 ccw(c186.096,86.36) 186.096,86.085 ccw(c186.096,86.36) 186.371,86.36 ccw(c186.096,86.36) 186.096,86.635 ccw(c186.096,86.36)
cut-out: 185.821,84.836 ccw(c186.096,84.836) 186.096,84.561 ccw(c186.096,84.836) 186.371,84.836 ccw(c186.096,84.836) 186.096,85.111 ccw(c186.096,84.836)
cut-out: 183.493,84.836 ccw(c183.768,84.836) 183.768,84.561 ccw(c183.768,84.836) 184.043,84.836 ccw(c183.768,84.836) 183.768,85.111 ccw(c183.768,84.836)
cut-out: 183.493,85.598 ccw(c183.768,85.598) 183.768,85.323 ccw(c183.768,85.598) 184.043,85.598 ccw(c183.768,85.598) 183.768,85.873 ccw(c183.768,85.598)
cut-out: 183.493,84.074 ccw(c183.768,84.074) 183.768,83.799 ccw(c183.768,84.074) 184.043,84.074 ccw(c183.768,84.074) 183.768,84.349 ccw(c183.768,84.074)
cut-out: 183.493,83.312 ccw(c183.768,83.312) 183.768,83.037 ccw(c183.768,83.312) 184.043,83.312 ccw(c183.768,83.312) 183.768,83.587 ccw(c183.768,83.312)
cut-out: 183.493,82.55 ccw(c183.768,82.55) 183.768,82.275 ccw(c183.768,82.55) 184.043,82.55 ccw(c183.768,82.55) 183.768,82.825 ccw(c183.768,82.55)
cut-out: 183.493,81.788 ccw(c183.768,81.788) 183.768,81.513 ccw(c183.768,81.788) 184.043,81.788 ccw(c183.768,81.788) 183.768,82.063 ccw(c183.768,81.788)
cut-out: 185.821,81.788 ccw(c186.096,81.788) 186.096,81.513 ccw(c186.096,81.788) 186.371,81.788 ccw(c186.096,81.788) 186.096,82.063 ccw(c186.096,81.788)
cut-out: 185.821,82.55 ccw(c186.096,82.55) 186.096,82.275 ccw(c186.096,82.55) 186.371,82.55 ccw(c186.096,82.55) 186.096,82.825 ccw(c186.096,82.55)
cut-out: 185.821,83.312 ccw(c186.096,83.312) 186.096,83.037 ccw(c186.096,83.312) 186.371,83.312 ccw(c186.096,83.312) 186.096,83.587 ccw(c186.096,83.312)
cut-out: 185.821,84.074 ccw(c186.096,84.074) 186.096,83.799 ccw(c186.096,84.074) 186.371,84.074 ccw(c186.096,84.074) 186.096,84.349 ccw(c186.096,84.074)
cut-out: 168.211,87.122 ccw(c168.486,87.122) 168.486,86.847 ccw(c168.486,87.122) 168.761,87.122 ccw(c168.486,87.122) 168.486,87.397 ccw(c168.486,87.122)
cut-out: 170.539,87.122 ccw(c170.814,87.122) 170.814,86.847 ccw(c170.814,87.122) 171.089,87.122 ccw(c170.814,87.122) 170.814,87.397 ccw(c170.814,87.122)
cut-out: 168.211,86.36 ccw(c168.486,86.36) 168.486,86.085 ccw(c168.486,86.36) 168.761,86.36 ccw(c168.486,86.36) 168.486,86.635 ccw(c168.486,86.36)
cut-out: 170.539,85.598 cw(c170.814,85.598) 170.814,85.873 cw(c170.814,85.598) 171.089,85.598 cw(c170.814,85.598) 170.814,85.323 cw(c170.814,85.598)
cut-out: 170.539,86.36 ccw(c170.814,86.36) 170.814,86.085 ccw(c170.814,86.36) 171.089,86.36 ccw(c170.814,86.36) 170.814,86.635 ccw(c170.814,86.36)
cut-out: 170.539,84.836 ccw(c170.814,84.836) 170.814,84.561 ccw(c170.814,84.836) 171.089,84.836 ccw(c170.814,84.836) 170.814,85.111 ccw(c170.814,84.836)
cut-out: 168.211,84.836 ccw(c168.486,84.836) 168.486,84.561 ccw(c168.486,84.836) 168.761,84.836 ccw(c168.486,84.836) 168.486,85.111 ccw(c168.486,84.836)
cut-out: 168.211,85.598 ccw(c168.486,85.598) 168.486,85.323 ccw(c168.486,85.598) 168.761,85.598 ccw(c168.486,85.598) 168.486,85.873 ccw(c168.486,85.598)
cut-out: 168.211,84.074 ccw(c168.486,84.074) 168.486,83.799 ccw(c168.486,84.074) 168.761,84.074 ccw(c168.486,84.074) 168.486,84.349 ccw(c168.486,84.074)
cut-out: 168.211,83.312 ccw(c168.486,83.312) 168.486,83.037 ccw(c168.486,83.312) 168.761,83.312 ccw(c168.486,83.312) 168.486,83.587 ccw(c168.486,83.312)
cut-out: 168.211,82.55 ccw(c168.486,82.55) 168.486,82.275 ccw(c168.486,82.55) 168.761,82.55 ccw(c168.486,82.55) 168.486,82.825 ccw(c168.486,82.55)
cut-out: 168.211,81.788 ccw(c168.486,81.788) 168.486,81.513 ccw(c168.486,81.788) 168.761,81.788 ccw(c168.486,81.788) 168.486,82.063 ccw(c168.486,81.788)
cut-out: 170.539,81.788 ccw(c170.814,81.788) 170.814,81.513 ccw(c170.814,81.788) 171.089,81.788 ccw(c170.814,81.788) 170.814,82.063 ccw(c170.814,81.788)
cut-out: 170.539,82.55 ccw(c170.814,82.55) 170.814,82.275 ccw(c170.814,82.55) 171.089,82.55 ccw(c170.814,82.55) 170.814,82.825 ccw(c170.814,82.55)
cut-out: 170.539,83.312 ccw(c170.814,83.312) 170.814,83.037 ccw(c170.814,83.312) 171.089,83.312 ccw(c170.814,83.312) 170.814,83.587 ccw(c170.814,83.312)
cut-out: 170.539,84.074 ccw(c170.814,84.074) 170.814,83.799 ccw(c170.814,84.074) 171.089,84.074 ccw(c170.814,84.074) 170.814,84.349 ccw(c170.814,84.074)
cut-out: 152.929,87.122 ccw(c153.204,87.122) 153.204,86.847 ccw(c153.204,87.122) 153.479,87.122 ccw(c153.204,87.122) 153.204,87.397 ccw(c153.204,87.122)
cut-out: 155.257,87.122 ccw(c155.532,87.122) 155.532,86.847 ccw(c155.532,87.122) 155.807,87.122 ccw(c155.532,87.122) 155.532,87.397 ccw(c155.532,87.122)
cut-out: 152.929,86.36 ccw(c153.204,86.36) 153.204,86.085 ccw(c153.204,86.36) 153.479,86.36 ccw(c153.204,86.36) 153.204,86.635 ccw(c153.204,86.36)
cut-out: 155.257,85.598 cw(c155.532,85.598) 155.532,85.873 cw(c155.532,85.598) 155.807,85.598 cw(c155.532,85.598) 155.532,85.323 cw(c155.532,85.598)
cut-out: 155.257,86.36 ccw(c155.532,86.36) 155.532,86.085 ccw(c155.532,86.36) 155.807,86.36 ccw(c155.532,86.36) 155.532,86.635 ccw(c155.532,86.36)
cut-out: 155.257,84.836 ccw(c155.532,84.836) 155.532,84.561 ccw(c155.532,84.836) 155.807,84.836 ccw(c155.532,84.836) 155.532,85.111 ccw(c155.532,84.836)
cut-out: 152.929,84.836 ccw(c153.204,84.836) 153.204,84.561 ccw(c153.204,84.836) 153.479,84.836 ccw(c153.204,84.836) 153.204,85.111 ccw(c153.204,84.836)
cut-out: 152.929,85.598 ccw(c153.204,85.598) 153.204,85.323 ccw(c153.204,85.598) 153.479,85.598 ccw(c153.204,85.598) 153.204,85.873 ccw(c153.204,85.598)
cut-out: 152.929,84.074 ccw(c153.204,84.074) 153.204,83.799 ccw(c153.204,84.074) 153.479,84.074 ccw(c153.204,84.074) 153.204,84.349 ccw(c153.204,84.074)
cut-out: 152.929,83.312 ccw(c153.204,83.312) 153.204,83.037 ccw(c153.204,83.312) 153.479,83.312 ccw(c153.204,83.312) 153.204,83.587 ccw(c153.204,83.312)
cut-out: 152.929,82.55 ccw(c153.204,82.55) 153.204,82.275 ccw(c153.204,82.55) 153.479,82.55 ccw(c153.204,82.55) 153.204,82.825 ccw(c153.204,82.55)
cut-out: 152.929,81.788 ccw(c153.204,81.788) 153.204,81.513 ccw(c153.204,81.788) 153.479,81.788 ccw(c153.204,81.788) 153.204,82.063 ccw(c153.204,81.788)
cut-out: 155.257,81.788 ccw(c155.532,81.788) 155.532,81.513 ccw(c155.532,81.788) 155.807,81.788 ccw(c155.532,81.788) 155.532,82.063 ccw(c155.532,81.788)
cut-out: 155.257,82.55 ccw(c155.532,82.55) 155.532,82.275 ccw(c155.532,82.55) 155.807,82.55 ccw(c155.532,82.55) 155.532,82.825 ccw(c155.532,82.55)
cut-out: 155.257,83.312 ccw(c155.532,83.312) 155.532,83.037 ccw(c155.532,83.312) 155.807,83.312 ccw(c155.532,83.312) 155.532,83.587 ccw(c155.532,83.312)
cut-out: 155.257,84.074 ccw(c155.532,84.074) 155.532,83.799 ccw(c155.532,84.074) 155.807,84.074 ccw(c155.532,84.074) 155.532,84.349 ccw(c155.532,84.074)
cut-out: 139.975,84.074 ccw(c140.25,84.074) 140.25,83.799 ccw(c140.25,84.074) 140.525,84.074 ccw(c140.25,84.074) 140.25,84.349 ccw(c140.25,84.074)
cut-out: 139.975,83.312 ccw(c140.25,83.312) 140.25,83.037 ccw(c140.25,83.312) 140.525,83.312 ccw(c140.25,83.312) 140.25,83.587 ccw(c140.25,83.312)
cut-out: 139.975,82.55 ccw(c140.25,82.55) 140.25,82.275 ccw(c140.25,82.55) 140.525,82.55 ccw(c140.25,82.55) 140.25,82.825 ccw(c140.25,82.55)
cut-out: 139.975,81.788 ccw(c140.25,81.788) 140.25,81.513 ccw(c140.25,81.788) 140.525,81.788 ccw(c140.25,81.788) 140.25,82.063 ccw(c140.25,81.788)
cut-out: 137.647,81.788 ccw(c137.922,81.788) 137.922,81.513 ccw(c137.922,81.788) 138.197,81.788 ccw(c137.922,81.788) 137.922,82.063 ccw(c137.922,81.788)
cut-out: 137.647,82.55 ccw(c137.922,82.55) 137.922,82.275 ccw(c137.922,82.55) 138.197,82.55 ccw(c137.922,82.55) 137.922,82.825 ccw(c137.922,82.55)
cut-out: 137.647,83.312 ccw(c137.922,83.312) 137.922,83.037 ccw(c137.922,83.312) 138.197,83.312 ccw(c137.922,83.312) 137.922,83.587 ccw(c137.922,83.312)
cut-out: 137.647,84.074 ccw(c137.922,84.074) 137.922,83.799 ccw(c137.922,84.074) 138.197,84.074 ccw(c137.922,84.074) 137.922,84.349 ccw(c137.922,84.074)
cut-out: 137.647,85.598 ccw(c137.922,85.598) 137.922,85.323 ccw(c137.922,85.598) 138.197,85.598 ccw(c137.922,85.598) 137.922,85.873 ccw(c137.922,85.598)
cut-out: 137.647,84.836 ccw(c137.922,84.836) 137.922,84.561 ccw(c137.922,84.836) 138.197,84.836 ccw(c137.922,84.836) 137.922,85.111 ccw(c137.922,84.836)
cut-out: 139.975,84.836 ccw(c140.25,84.836) 140.25,84.561 ccw(c140.25,84.836) 140.525,84.836 ccw(c140.25,84.836) 140.25,85.111 ccw(c140.25,84.836)
cut-out: 139.975,86.36 ccw(c140.25,86.36) 140.25,86.085 ccw(c140.25,86.36) 140.525,86.36 ccw(c140.25,86.36) 140.25,86.635 ccw(c140.25,86.36)
cut-out: 139.975,85.598 cw(c140.25,85.598) 140.25,85.873 cw(c140.25,85.598) 140.525,85.598 cw(c140.25,85.598) 140.25,85.323 cw(c140.25,85.598)
cut-out: 137.647,86.36 ccw(c137.922,86.36) 137.922,86.085 ccw(c137.922,86.36) 138.197,86.36 ccw(c137.922,86.36) 137.922,86.635 ccw(c137.922,86.36)
cut-out: 139.975,87.122 ccw(c140.25,87.122) 140.25,86.847 ccw(c140.25,87.122) 140.525,87.122 ccw(c140.25,87.122) 140.25,87.397 ccw(c140.25,87.122)
cut-out: 137.647,87.122 ccw(c137.922,87.122) 137.922,86.847 ccw(c137.922,87.122) 138.197,87.122 ccw(c137.922,87.122) 137.922,87.397 ccw(c137.922,87.122)
cut-out: 134.747,71.713 134.747,74.295 137.795,74.295 137.795,81.153 140.377,81.153 140.377,74.295 143.425,74.295 143.425,71.713 140.377,71.713 140.377,64.855 137.795,64.855 137.795,71.713
cut-out: 150.029,71.713 150.029,74.295 153.077,74.295 153.077,81.153 155.659,81.153 155.659,74.295 158.707,74.295 158.707,71.713 155.659,71.713 155.659,64.855 153.077,64.855 153.077,71.713
cut-out: 134.747,71.713 134.747,74.295 137.795,74.295 137.795,81.153 140.377,81.153 140.377,74.295 143.425,74.295 143.425,71.713 140.377,71.713 140.377,64.855 137.795,64.855 137.795,71.713
cut-out: 168.359,64.855 168.359,71.713 165.311,71.713 165.311,74.295 168.359,74.295 168.359,81.153 170.941,81.153 170.941,74.295 173.989,74.295 173.989,71.713 170.941,71.713 170.941,64.855
cut-out: 183.641,64.855 183.641,71.713 180.593,71.713 180.593,74.295 183.641,74.295 183.641,81.153 186.223,81.153 186.223,74.295 189.271,74.295 189.271,71.713 186.223,71.713 186.223,64.855
cut-out: 198.923,64.855 198.923,71.713 195.875,71.713 195.875,74.295 198.923,74.295 198.923,81.153 201.505,81.153 201.505,74.295 204.553,74.295 204.553,71.713 201.505,71.713 201.505,64.855
cut-out: 150.029,48.811 150.029,51.393 153.077,51.393 153.077,58.251 155.659,58.251 155.659,51.393 158.707,51.393 158.707,48.811 155.659,48.811 155.659,41.953 153.077,41.953 153.077,48.811
cut-out: 168.359,41.953 168.359,48.811 165.311,48.811 165.311,51.393 168.359,51.393 168.359,58.251 170.941,58.251 170.941,51.393 173.989,51.393 173.989,48.811 170.941,48.811 170.941,41.953
cut-out: 183.641,41.953 183.641,48.811 180.593,48.811 180.593,51.393 183.641,51.393 183.641,58.251 186.223,58.251 186.223,51.393 189.271,51.393 189.271,48.811 186.223,48.811 186.223,41.953
cut-out: 198.923,41.953 198.923,48.811 195.875,48.811 195.875,51.393 198.923,51.393 198.923,58.251 201.505,58.251 201.505,51.393 204.553,51.393 204.553,48.811 201.505,48.811 201.505,41.953
cut-out: 134.747,25.909 134.747,28.491 137.795,28.491 137.795,35.349 140.377,35.349 140.377,28.491 143.425,28.491 143.425,25.909 140.377,25.909 140.377,19.051 137.795,19.051 137.795,25.909
cut-out: 150.029,25.909 150.029,28.491 153.077,28.491 153.077,35.349 155.659,35.349 155.659,28.491 158.707,28.491 158.707,25.909 155.659,25.909 155.659,19.051 153.077,19.051 153.077,25.909
cut-out: 165.311,25.909 165.311,28.491 168.359,28.491 168.359,35.349 170.941,35.349 170.941,28.491 173.989,28.491 173.989,25.909 170.941,25.909 170.941,19.051 168.359,19.051 168.359,25.909
cut-out: 180.593,25.909 180.593,28.491 183.641,28.491 183.641,35.349 186.223,35.349 186.223,28.491 189.271,28.491 189.271,25.909 186.223,25.909 186.223,19.051 183.641,19.051 183.641,25.909
cut-out: 195.875,25.909 195.875,28.491 198.923,28.491 198.923,35.349 201.505,35.349 201.505,28.491 204.553,28.491 204.553,25.909 201.505,25.909 201.505,19.051 198.923,19.051 198.923,25.909
cut-out: 134.747,48.811 134.747,51.393 137.795,51.393 137.795,58.251 140.377,58.251 140.377,51.393 143.425,51.393 143.425,48.811 140.377,48.811 140.377,41.953 137.795,41.953 137.795,48.811
cut-out: 125.095,71.586 137.668,71.586 137.668,64.855 ccw(c137.795,64.855) 137.795,64.728 140.377,64.728 ccw(c140.377,64.855) 140.504,64.855 140.504,71.713 ccw(c140.377,71.713) 140.25,71.713 140.25,64.982 137.922,64.982 137.922,71.713 ccw(c137.795,71.713) 137.795,71.84 134.874,71.84 134.874,74.168 137.795,74.168 ccw(c137.795,74.295) 137.922,74.295 137.922,81.026 140.25,81.026 140.25,74.295 ccw(c140.377,74.295) 140.377,74.168 153.077,74.168 ccw(c153.077,74.295) 153.204,74.295 ccw(c153.077,74.295) 153.077,74.422 140.504,74.422 140.504,81.153 ccw(c140.377,81.153) 140.377,81.28 137.795,81.28 ccw(c137.795,81.153) 137.668,81.153 137.668,74.422 125.095,74.422 ccw(c125.095,74.295) 125.095,74.168 134.62,74.168 134.62,71.84 125.095,71.84 ccw(c125.095,71.713)
cut-out: 134.62,71.713 ccw(c134.747,71.713) 134.747,71.586 137.668,71.586 137.668,64.855 ccw(c137.795,64.855) 137.922,64.855 137.922,71.713 ccw(c137.795,71.713) 137.795,71.84 134.874,71.84 134.874,74.168 137.795,74.168 ccw(c137.795,74.295) 137.922,74.295 137.922,81.026 140.25,81.026 140.25,74.295 ccw(c140.377,74.295) 140.377,74.168 143.298,74.168 143.298,71.84 140.377,71.84 ccw(c140.377,71.713) 140.25,71.713 140.25,64.855 ccw(c140.377,64.855) 140.504,64.855 140.504,71.586 143.425,71.586 ccw(c143.425,71.713) 143.552,71.713 143.552,74.295 ccw(c143.425,74.295) 143.425,74.422 140.504,74.422 140.504,81.153 ccw(c140.377,81.153) 140.377,81.28 137.795,81.28 ccw(c137.795,81.153) 137.668,81.153 137.668,74.422 134.747,74.422 ccw(c134.747,74.295) 134.62,74.295
cut-out: 137.668,41.953 ccw(c137.795,41.953) 137.795,41.826 140.377,41.826 ccw(c140.377,41.953) 140.504,41.953 140.504,48.684 143.425,48.684 ccw(c143.425,48.811) 143.552,48.811 143.552,51.393 ccw(c143.425,51.393) 143.425,51.52 140.504,51.52 140.504,58.251 ccw(c140.377,58.251) 140.377,58.378 137.795,58.378 ccw(c137.795,58.251) 137.668,58.251 137.668,51.393 ccw(c137.795,51.393) 137.922,51.393 137.922,58.124 140.25,58.124 140.25,51.393 ccw(c140.377,51.393) 140.377,51.266 143.298,51.266 143.298,48.938 140.377,48.938 ccw(c140.377,48.811) 140.25,48.811 140.25,42.08 137.922,42.08 137.922,48.811 ccw(c137.795,48.811) 137.668,48.811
